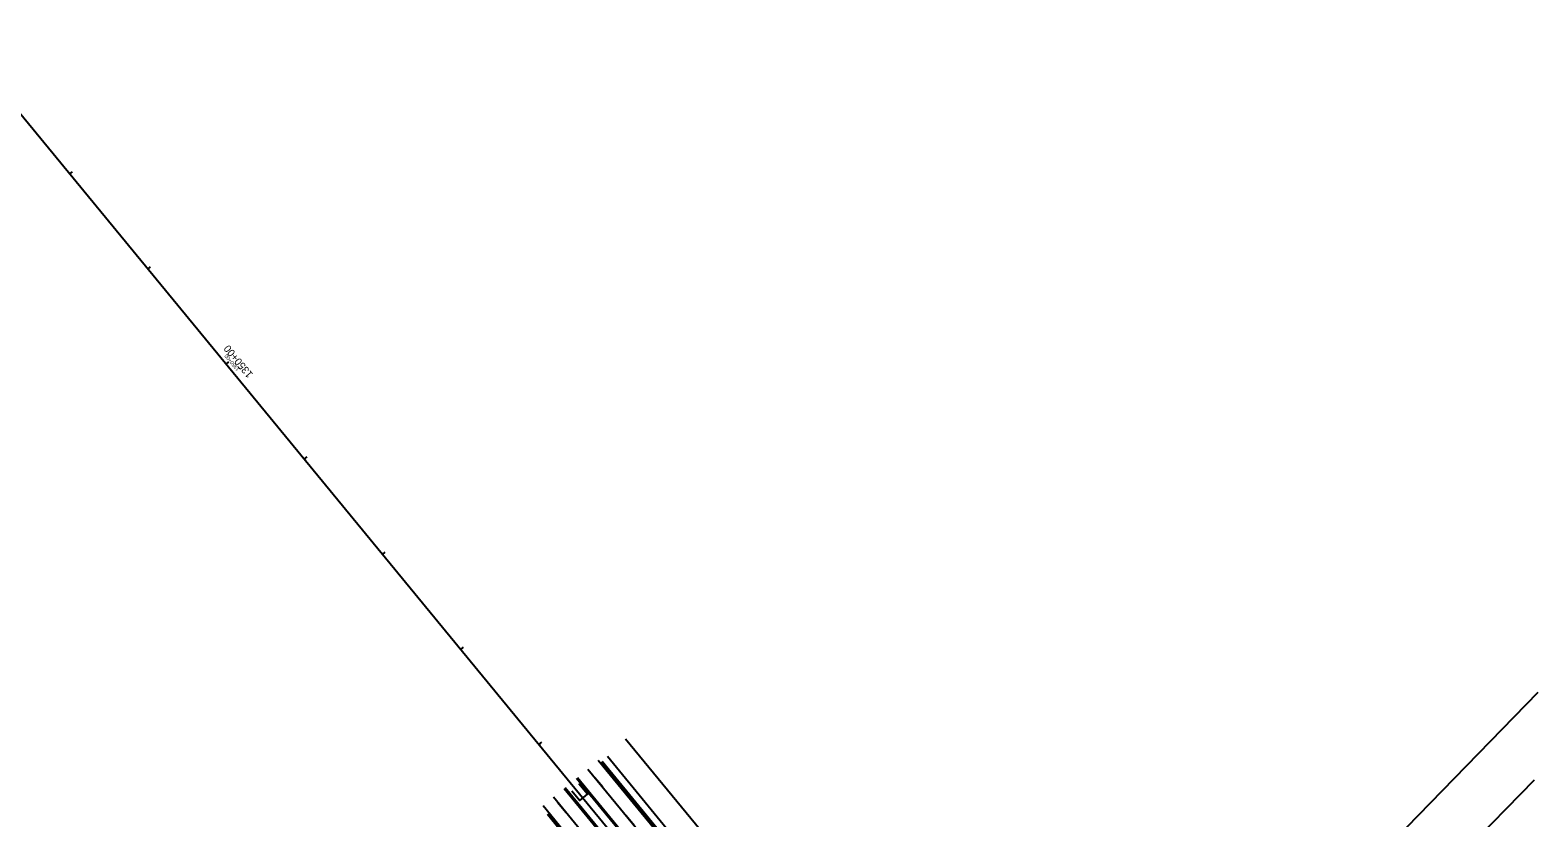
# Model space of a CAD drawing. Extents: x 2252205 to 2259955, y 13788514 to 13798103.
# Drawn here: x 2255600 to 2256824, y 13792642 to 13793282 of the extents above; entities that cross this region are included whole.
import ezdxf

# ---------------------------------------------------------------- set-up
doc = ezdxf.new("R2010")
doc.units = 0
for name, color, linetype in [('D_RDWY_TRACK_P_AND_T', 7, 'Continuous'), ('GEOM_CENTERLINE_ALIGN', 7, 'Continuous'), ('GEOM_CENTERLINE_STA_100', 7, 'Continuous'), ('GEOM_CENTERLINE_STA_50', 7, 'Continuous'), ('Road_Curb_Back', 7, 'Continuous'), ('Road_Curb_Face', 7, 'Continuous'), ('Road_EdgeOfPavementOutside', 7, 'Continuous'), ('ROAD_PAVMRK_Y_4IN_BRK', 7, 'Continuous'), ('ROAD_ROW_EXIST', 7, 'Continuous'), ('Road_Sidewalk_Back', 7, 'Continuous'), ('TRAF_PAVMRK_W_4IN_BRK', 7, 'Continuous'), ('TRAF_PAVMRK_W_4IN_SLD', 7, 'Continuous'), ('TRAF_PAVMRK_Y_4IN_SLD', 7, 'Continuous')]:
    doc.layers.add(name, color=color, linetype=linetype)

msp = doc.modelspace()

# ---------------------------------------------------------------- linework, layer by layer
at = {"layer": 'D_RDWY_TRACK_P_AND_T'}
msp.add_lwpolyline([(2256039.7, 13792663.8), (2256046.1, 13792656), (2256052.3, 13792661.1), (2256045.4, 13792669.4)], dxfattribs=at)
at = {"layer": 'GEOM_CENTERLINE_ALIGN'}
msp.add_line((2256266.5, 13792392.9), (2254123.8, 13794999.8), dxfattribs=at)
at = {"layer": 'GEOM_CENTERLINE_STA_100'}
for p, q in [((2255631.9, 13793164.9), (2255634.2, 13793166.8)), ((2255695.4, 13793087.7), (2255697.7, 13793089.6)), ((2255758.9, 13793010.4), (2255761.2, 13793012.3)), ((2255822.4, 13792933.2), (2255824.7, 13792935.1)), ((2255885.9, 13792855.9), (2255888.2, 13792857.8)), ((2255949.4, 13792778.7), (2255951.7, 13792780.6)), ((2256012.9, 13792701.4), (2256015.2, 13792703.3))]:
    msp.add_line(p, q, dxfattribs=at)
at = {"layer": 'GEOM_CENTERLINE_STA_50'}
for p, q in [((2255631.9, 13793164.9), (2255633.1, 13793165.9)), ((2255695.4, 13793087.7), (2255696.6, 13793088.6)), ((2255758.9, 13793010.4), (2255760.1, 13793011.4)), ((2255822.4, 13792933.2), (2255823.6, 13792934.1)), ((2255885.9, 13792855.9), (2255887.1, 13792856.9)), ((2255949.4, 13792778.7), (2255950.6, 13792779.6)), ((2256012.9, 13792701.4), (2256014.1, 13792702.4))]:
    msp.add_line(p, q, dxfattribs=at)
at = {"layer": 'Road_Curb_Back'}
for p, q in [((2256290.3, 13792412.5), (2256064.2, 13792687.6)), ((2256052.6, 13792604.6), (2256019.8, 13792644.5))]:
    msp.add_line(p, q, dxfattribs=at)
at = {"layer": 'Road_Curb_Face'}
for p, q in [((2256289.7, 13792412), (2256063.6, 13792687)), ((2256053.2, 13792605.1), (2256020.4, 13792645.1))]:
    msp.add_line(p, q, dxfattribs=at)
at = {"layer": 'Road_EdgeOfPavementOutside'}
for p, q in [((2256289.7, 13792412), (2256063.6, 13792687)), ((2256053.2, 13792605.1), (2256020.4, 13792645.1))]:
    msp.add_line(p, q, dxfattribs=at)
at = {"layer": 'ROAD_PAVMRK_Y_4IN_BRK'}
for p, q in [((2256081, 13792628), (2256043.3, 13792673.9)), ((2256071.8, 13792620.4), (2256034.1, 13792666.2))]:
    msp.add_line(p, q, dxfattribs=at)
for points in [[(2256046.4, 13792651.3), (2256040, 13792659)], [(2256055.6, 13792658.9), (2256049.3, 13792666.6)], [(2256055.6, 13792658.9), (2256055.6, 13792658.9)], [(2256046.4, 13792651.3), (2256046.4, 13792651.3)]]:
    msp.add_lwpolyline(points, dxfattribs=at)
at = {"layer": 'ROAD_ROW_EXIST'}
for p, q in [((2256823.8, 13792743.6), (2256564.6, 13792477.7)), ((2256083.3, 13792706.2), (2256400.2, 13792320.7)), ((2256820.8, 13792672.6), (2256436.4, 13792279.2))]:
    msp.add_line(p, q, dxfattribs=at)
at = {"layer": 'Road_Sidewalk_Back'}
msp.add_line((2256294.9, 13792416.3), (2256068.5, 13792691.8), dxfattribs=at)
at = {"layer": 'TRAF_PAVMRK_W_4IN_BRK'}
for p, q in [((2256052.6, 13792681.5), (2256280.4, 13792404.4)), ((2256252.6, 13792381.5), (2256024.8, 13792658.6))]:
    msp.add_line(p, q, dxfattribs=at)
for points in [[(2256064.7, 13792666.7), (2256058.4, 13792674.4)], [(2256064.7, 13792666.7), (2256064.7, 13792666.7)], [(2256028.3, 13792654.3), (2256034.7, 13792646.6)], [(2256028.3, 13792654.3), (2256028.3, 13792654.3)], [(2256090.1, 13792635.8), (2256083.8, 13792643.5)]]:
    msp.add_lwpolyline(points, dxfattribs=at)
at = {"layer": 'TRAF_PAVMRK_W_4IN_SLD'}
for p, q in [((2256288.9, 13792411.3), (2256061.1, 13792688.5)), ((2256054, 13792605.7), (2256016.3, 13792651.6))]:
    msp.add_line(p, q, dxfattribs=at)
at = {"layer": 'TRAF_PAVMRK_Y_4IN_SLD'}
for p, q in [((2256271.9, 13792397.4), (2256044.1, 13792674.5)), ((2256118.7, 13792561.6), (2256033.3, 13792665.6))]:
    msp.add_line(p, q, dxfattribs=at)

# ---------------------------------------------------------------- texts
at = {"layer": 'GEOM_CENTERLINE_STA_100'}
msp.add_text('1350+00', height=6, rotation=129.4186, dxfattribs=at).set_placement((2255781.1, 13793002.3))
at = {"layer": 'GEOM_CENTERLINE_STA_50'}
msp.add_text('1350+00', height=3, rotation=129.4186, dxfattribs=at).set_placement((2255770, 13793006.4))

doc.saveas('drawing.dxf')
